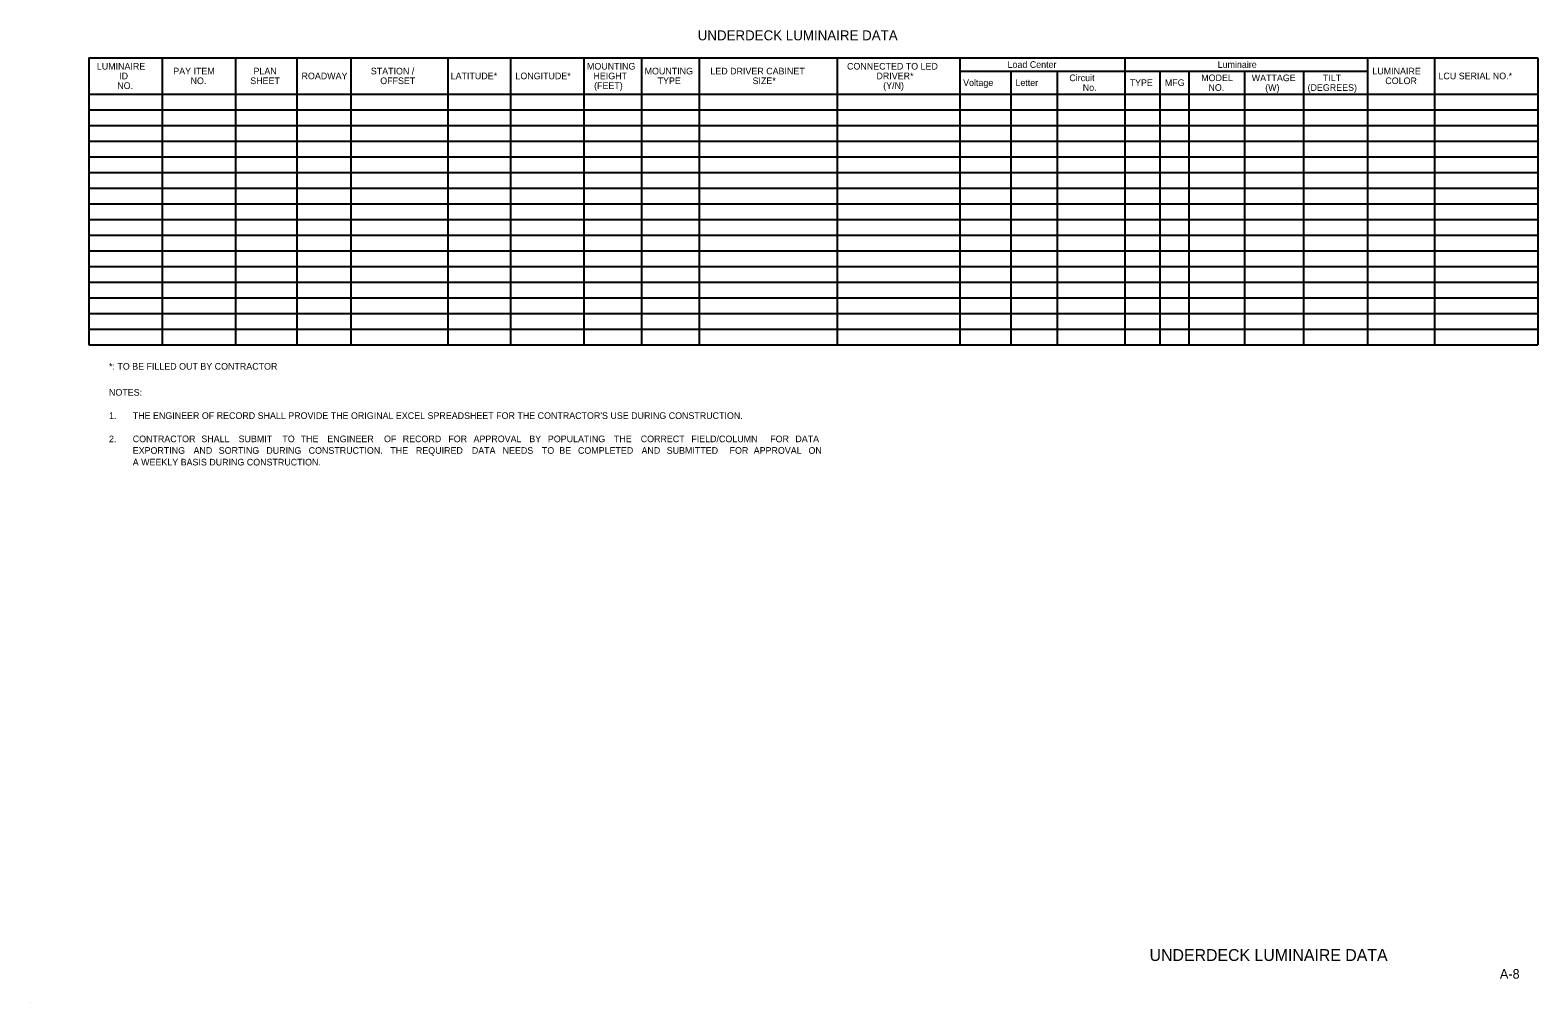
# Model space of a CAD drawing. Extents: x -830028.7 to -830012.8, y 1290283.4 to 1290293.7.
import ezdxf

# ---------------------------------------------------------------- set-up
doc = ezdxf.new("R2010")
doc.units = 0
for name, color, linetype in [('AdhocPoint_dp', 7, 'Continuous'), ('SumBoxBorder_dp', 7, 'Continuous'), ('SumBoxLines_dp', 7, 'Continuous'), ('SumBoxLinesMin_dp', 7, 'Continuous'), ('TextLabel', 7, 'Continuous'), ('TextMisc', 7, 'Continuous'), ('TextNotes', 7, 'Continuous'), ('TextShtNo', 7, 'Continuous')]:
    doc.layers.add(name, color=color, linetype=linetype)

msp = doc.modelspace()

# ---------------------------------------------------------------- linework, layer by layer
at = {"layer": 'AdhocPoint_dp'}
msp.add_line((-830028.694, 1290283.415), (-830028.694, 1290283.415), dxfattribs=at)
at = {"layer": 'SumBoxBorder_dp'}
for p, q in [((-830028.075, 1290293.368), (-830012.812, 1290293.368)), ((-830028.075, 1290293.368), (-830012.812, 1290293.368)), ((-830028.075, 1290293.368), (-830028.075, 1290290.345)), ((-830027.302, 1290293.368), (-830027.302, 1290292.985)), ((-830027.302, 1290293.368), (-830027.302, 1290292.985)), ((-830026.53, 1290293.368), (-830026.53, 1290292.985)), ((-830026.53, 1290293.368), (-830026.53, 1290292.985)), ((-830025.885, 1290293.368), (-830025.885, 1290292.985)), ((-830025.885, 1290293.368), (-830025.885, 1290292.985)), ((-830025.315, 1290293.368), (-830025.315, 1290292.985)), ((-830025.315, 1290293.368), (-830025.315, 1290292.985)), ((-830024.295, 1290293.368), (-830024.295, 1290292.985)), ((-830024.295, 1290293.368), (-830024.295, 1290292.985)), ((-830023.635, 1290293.368), (-830023.635, 1290292.985)), ((-830023.635, 1290293.368), (-830023.635, 1290292.985)), ((-830022.862, 1290293.368), (-830022.862, 1290292.985)), ((-830022.862, 1290293.368), (-830022.862, 1290292.985)), ((-830022.255, 1290293.368), (-830022.255, 1290292.985)), ((-830022.255, 1290293.368), (-830022.255, 1290292.985)), ((-830021.647, 1290293.368), (-830021.647, 1290292.985)), ((-830021.647, 1290293.368), (-830021.647, 1290292.985)), ((-830020.192, 1290293.368), (-830020.192, 1290292.985)), ((-830020.192, 1290293.368), (-830020.192, 1290292.985)), ((-830018.902, 1290293.368), (-830018.902, 1290292.985)), ((-830018.902, 1290293.368), (-830018.902, 1290292.985)), ((-830017.162, 1290293.368), (-830017.162, 1290292.985)), ((-830017.162, 1290293.368), (-830017.162, 1290292.985)), ((-830014.605, 1290293.368), (-830014.605, 1290292.985)), ((-830014.605, 1290293.368), (-830014.605, 1290292.985)), ((-830012.812, 1290293.368), (-830012.812, 1290290.345)), ((-830018.902, 1290293.225), (-830014.605, 1290293.225)), ((-830018.902, 1290293.225), (-830014.605, 1290293.225)), ((-830018.362, 1290293.225), (-830018.362, 1290292.985)), ((-830018.362, 1290293.225), (-830018.362, 1290292.985)), ((-830017.875, 1290293.225), (-830017.875, 1290292.985)), ((-830017.875, 1290293.225), (-830017.875, 1290292.985)), ((-830016.795, 1290293.225), (-830016.795, 1290292.985)), ((-830016.795, 1290293.225), (-830016.795, 1290292.985)), ((-830016.487, 1290293.225), (-830016.487, 1290292.985)), ((-830016.487, 1290293.225), (-830016.487, 1290292.985)), ((-830015.902, 1290293.225), (-830015.902, 1290292.985)), ((-830015.902, 1290293.225), (-830015.902, 1290292.985)), ((-830015.28, 1290293.225), (-830015.28, 1290292.985)), ((-830015.28, 1290293.225), (-830015.28, 1290292.985)), ((-830028.075, 1290292.985), (-830012.812, 1290292.985)), ((-830028.075, 1290292.985), (-830020.192, 1290292.985)), ((-830018.902, 1290292.985), (-830012.812, 1290292.985)), ((-830028.075, 1290290.345), (-830012.812, 1290290.345))]:
    msp.add_line(p, q, dxfattribs=at)
at = {"layer": 'SumBoxLines_dp'}
for p, q in [((-830013.9, 1290293.368), (-830013.9, 1290290.345)), ((-830013.9, 1290293.368), (-830013.9, 1290290.345)), ((-830027.302, 1290292.985), (-830027.302, 1290290.345)), ((-830027.302, 1290292.985), (-830027.302, 1290290.345)), ((-830026.53, 1290292.985), (-830026.53, 1290290.345)), ((-830026.53, 1290292.985), (-830026.53, 1290290.345)), ((-830025.885, 1290292.985), (-830025.885, 1290290.345)), ((-830025.885, 1290292.985), (-830025.885, 1290290.345)), ((-830025.315, 1290292.985), (-830025.315, 1290290.345)), ((-830025.315, 1290292.985), (-830025.315, 1290290.345)), ((-830024.295, 1290292.985), (-830024.295, 1290290.345)), ((-830024.295, 1290292.985), (-830024.295, 1290290.345)), ((-830023.635, 1290292.985), (-830023.635, 1290290.345)), ((-830023.635, 1290292.985), (-830023.635, 1290290.345)), ((-830022.862, 1290292.985), (-830022.862, 1290290.345)), ((-830022.862, 1290292.985), (-830022.862, 1290290.345)), ((-830022.255, 1290292.985), (-830022.255, 1290290.345)), ((-830022.255, 1290292.985), (-830022.255, 1290290.345)), ((-830021.647, 1290292.985), (-830021.647, 1290290.345)), ((-830021.647, 1290292.985), (-830021.647, 1290290.345)), ((-830020.192, 1290292.985), (-830020.192, 1290290.345)), ((-830020.192, 1290292.985), (-830020.192, 1290290.345)), ((-830018.902, 1290292.985), (-830018.902, 1290290.345)), ((-830018.902, 1290292.985), (-830018.902, 1290290.345)), ((-830018.362, 1290292.985), (-830018.362, 1290290.345)), ((-830018.362, 1290292.985), (-830018.362, 1290290.345)), ((-830017.875, 1290292.985), (-830017.875, 1290290.345)), ((-830017.875, 1290292.985), (-830017.875, 1290290.345)), ((-830017.162, 1290292.985), (-830017.162, 1290290.345)), ((-830017.162, 1290292.985), (-830017.162, 1290290.345)), ((-830016.795, 1290292.985), (-830016.795, 1290290.345)), ((-830016.795, 1290292.985), (-830016.795, 1290290.345)), ((-830016.487, 1290292.985), (-830016.487, 1290290.345)), ((-830016.487, 1290292.985), (-830016.487, 1290290.345)), ((-830015.902, 1290292.985), (-830015.902, 1290290.345)), ((-830015.902, 1290292.985), (-830015.902, 1290290.345)), ((-830015.28, 1290292.985), (-830015.28, 1290290.345)), ((-830015.28, 1290292.985), (-830015.28, 1290290.345)), ((-830014.605, 1290292.985), (-830014.605, 1290290.345)), ((-830014.605, 1290292.985), (-830014.605, 1290290.345))]:
    msp.add_line(p, q, dxfattribs=at)
at = {"layer": 'SumBoxLinesMin_dp'}
for p, q in [((-830020.192, 1290292.985), (-830018.902, 1290292.985)), ((-830028.075, 1290292.82), (-830012.812, 1290292.82)), ((-830028.075, 1290292.82), (-830012.812, 1290292.82)), ((-830028.075, 1290292.655), (-830012.812, 1290292.655)), ((-830028.075, 1290292.655), (-830012.812, 1290292.655)), ((-830028.075, 1290292.49), (-830012.812, 1290292.49)), ((-830028.075, 1290292.49), (-830012.812, 1290292.49)), ((-830028.075, 1290292.325), (-830012.812, 1290292.325)), ((-830028.075, 1290292.325), (-830012.812, 1290292.325)), ((-830028.075, 1290292.16), (-830012.812, 1290292.16)), ((-830028.075, 1290292.16), (-830012.812, 1290292.16)), ((-830028.075, 1290291.995), (-830012.812, 1290291.995)), ((-830028.075, 1290291.995), (-830012.812, 1290291.995)), ((-830028.075, 1290291.83), (-830012.812, 1290291.83)), ((-830028.075, 1290291.83), (-830012.812, 1290291.83)), ((-830028.075, 1290291.665), (-830012.812, 1290291.665)), ((-830028.075, 1290291.665), (-830012.812, 1290291.665)), ((-830028.075, 1290291.5), (-830012.812, 1290291.5)), ((-830028.075, 1290291.335), (-830012.812, 1290291.335)), ((-830028.075, 1290291.17), (-830012.812, 1290291.17)), ((-830028.075, 1290291.005), (-830012.812, 1290291.005)), ((-830028.075, 1290290.84), (-830012.812, 1290290.84)), ((-830028.075, 1290290.675), (-830012.812, 1290290.675)), ((-830028.075, 1290290.51), (-830012.812, 1290290.51))]:
    msp.add_line(p, q, dxfattribs=at)

# ---------------------------------------------------------------- texts
at = {"layer": 'TextLabel'}
for s, height, p in [('UNDERDECK LUMINAIRE DATA', 0.105, (-830021.662, 1290293.551)), ('LUMINAIRE', 0.07, (-830027.991, 1290293.243)), ('MOUNTING', 0.07, (-830022.828, 1290293.243)), ('CONNECTED TO LED', 0.07, (-830020.089, 1290293.243)), ('Load Center', 0.07, (-830018.398, 1290293.261)), ('Luminaire', 0.07, (-830016.185, 1290293.261)), ('ID', 0.07, (-830027.756, 1290293.141)), ('PAY ITEM', 0.07, (-830027.186, 1290293.192)), ('NO.', 0.07, (-830027.004, 1290293.09)), ('SHEET', 0.07, (-830026.375, 1290293.09)), ('PLAN', 0.07, (-830026.341, 1290293.192)), ('ROADWAY', 0.07, (-830025.835, 1290293.141)), ('STATION /', 0.07, (-830025.105, 1290293.192)), ('OFFSET', 0.07, (-830025.006, 1290293.09)), ('LATITUDE*', 0.07, (-830024.264, 1290293.141)), ('LONGITUDE*', 0.07, (-830023.582, 1290293.141)), ('HEIGHT', 0.07, (-830022.76, 1290293.141)), ('MOUNTING', 0.07, (-830022.221, 1290293.192)), ('TYPE', 0.07, (-830022.084, 1290293.09)), ('LED DRIVER CABINET', 0.07, (-830021.528, 1290293.192)), ('SIZE*', 0.07, (-830021.084, 1290293.09)), ('DRIVER*', 0.07, (-830019.779, 1290293.141)), ('Voltage', 0.07, (-830018.866, 1290293.07)), ('Letter', 0.07, (-830018.315, 1290293.07)), ('Circuit', 0.07, (-830017.747, 1290293.121)), ('TYPE', 0.07, (-830017.112, 1290293.07)), ('MFG', 0.07, (-830016.741, 1290293.07)), ('MODEL', 0.07, (-830016.358, 1290293.121)), ('WATTAGE', 0.07, (-830015.826, 1290293.121)), ('TILT', 0.07, (-830015.076, 1290293.121)), ('LUMINAIRE', 0.07, (-830014.555, 1290293.192)), ('COLOR', 0.07, (-830014.419, 1290293.09)), ('LCU SERIAL NO.*', 0.07, (-830013.859, 1290293.141)), ('NO.', 0.07, (-830027.776, 1290293.039)), ('(FEET)', 0.07, (-830022.753, 1290293.039)), ('(Y/N)', 0.07, (-830019.708, 1290293.039)), ('No.', 0.07, (-830017.606, 1290293.019)), ('NO.', 0.07, (-830016.282, 1290293.019)), ('(W)', 0.07, (-830015.684, 1290293.019)), ('(DEGREES)', 0.07, (-830015.238, 1290293.019))]:
    msp.add_text(s, height=height, dxfattribs=at).set_placement(p)
at = {"layer": 'TextMisc'}
msp.add_text('UNDERDECK LUMINAIRE DATA ', height=0.125, dxfattribs=at).set_placement((-830016.902, 1290283.856))
at = {"layer": 'TextNotes'}
for s, p in [('*: TO BE FILLED OUT BY CONTRACTOR', (-830027.863, 1290290.083)), ('NOTES:', (-830027.863, 1290289.809)), ('1.', (-830027.863, 1290289.564)), ("THE ENGINEER OF RECORD SHALL PROVIDE THE ORIGINAL EXCEL SPREADSHEET FOR THE CONTRACTOR'S USE DURING CONSTRUCTION.", (-830027.613, 1290289.564)), ('2.', (-830027.863, 1290289.319)), ('CONTRACTOR ', (-830027.613, 1290289.319)), ('SHALL ', (-830026.89, 1290289.319)), ('SUBMIT ', (-830026.498, 1290289.319)), ('TO ', (-830026.037, 1290289.319)), ('THE ', (-830025.844, 1290289.319)), ('ENGINEER ', (-830025.563, 1290289.319)), ('OF ', (-830024.966, 1290289.319)), ('RECORD ', (-830024.769, 1290289.319)), ('FOR ', (-830024.289, 1290289.319)), ('APPROVAL ', (-830024.023, 1290289.319)), ('BY ', (-830023.436, 1290289.319)), ('POPULATING ', (-830023.24, 1290289.319)), ('THE ', (-830022.544, 1290289.319)), ('CORRECT ', (-830022.262, 1290289.319)), ('FIELD/COLUMN ', (-830021.729, 1290289.319)), ('FOR ', (-830020.898, 1290289.319)), ('DATA ', (-830020.633, 1290289.319)), ('A WEEKLY BASIS DURING CONSTRUCTION. ', (-830027.613, 1290289.074)), ('EXPORTING ', (-830027.613, 1290289.197)), ('AND ', (-830026.973, 1290289.197)), ('SORTING ', (-830026.707, 1290289.197)), ('DURING ', (-830026.206, 1290289.197)), ('CONSTRUCTION. ', (-830025.76, 1290289.197)), ('THE ', (-830024.9, 1290289.197)), ('REQUIRED ', (-830024.63, 1290289.197)), ('DATA ', (-830024.041, 1290289.197)), ('NEEDS ', (-830023.717, 1290289.197)), ('TO ', (-830023.303, 1290289.197)), ('BE ', (-830023.12, 1290289.197)), ('COMPLETED ', (-830022.923, 1290289.197)), ('AND ', (-830022.254, 1290289.197)), ('SUBMITTED ', (-830021.988, 1290289.197)), ('FOR ', (-830021.326, 1290289.197)), ('APPROVAL ', (-830021.072, 1290289.197)), ('ON ', (-830020.495, 1290289.197))]:
    msp.add_text(s, height=0.07, dxfattribs=at).set_placement(p)
at = {"layer": 'TextShtNo'}
msp.add_text('A-8', height=0.1, dxfattribs=at).set_placement((-830013.212, 1290283.67))

doc.saveas('drawing.dxf')
